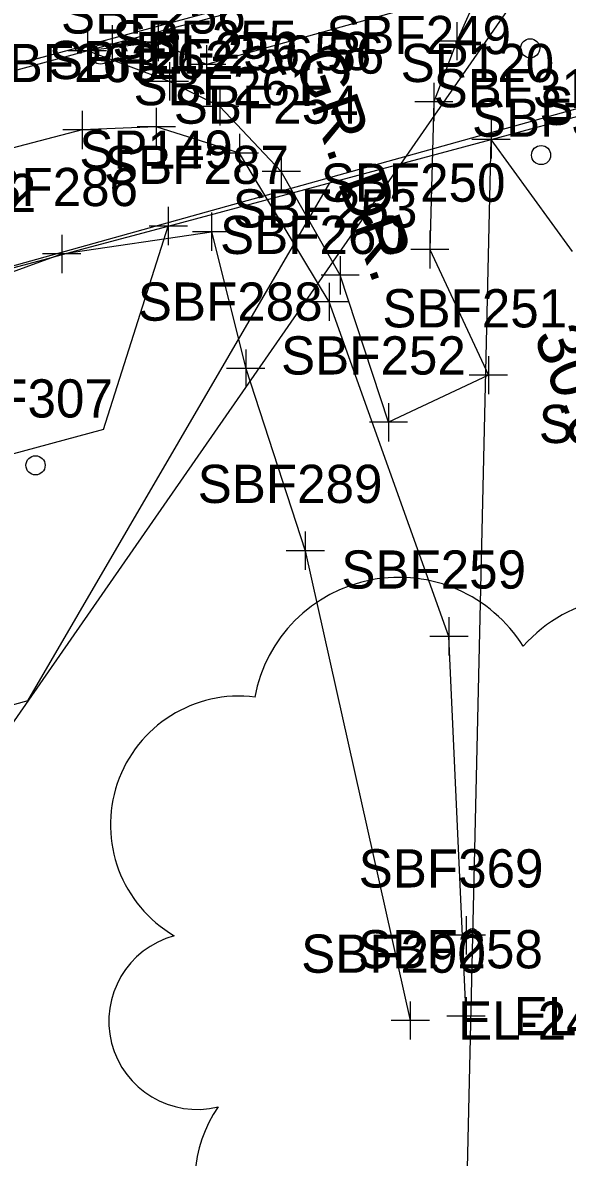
# Model space of a CAD drawing. Extents: x 818717 to 846077, y 440014 to 541392.
# Drawn here: x 831689.4 to 831746.3, y 492977.1 to 493095.8 of the extents above; entities that cross this region are included whole.
import ezdxf

# ---------------------------------------------------------------- set-up
doc = ezdxf.new("R2010")
doc.units = 0
for name, color, linetype in [('SURVEY - CENTERLINE - Preliminary', 7, 'Continuous'), ('SURVEY - CENTERLINE - Preliminary Text', 7, 'Continuous'), ('SURVEY - DRAINAGE - Bridge Hydraulic Data - Points - Numbers', 7, 'Continuous'), ('SURVEY - DTM - Breaklines', 7, 'Continuous'), ('SURVEY - DTM - Breaklines - Points - Elevations', 7, 'Continuous'), ('SURVEY - DTM - Breaklines - Points - Locators', 7, 'Continuous'), ('SURVEY - DTM - Breaklines - Points - Numbers', 7, 'Continuous'), ('SURVEY - DTM - Spot Points - Elevations', 7, 'Continuous'), ('SURVEY - DTM - Spot Points - Locators', 7, 'Continuous'), ('SURVEY - DTM - Spot Points - Point Numbers', 7, 'Continuous'), ('SURVEY - PROPERTY - Property Lines', 7, 'Continuous'), ('SURVEY - PROPERTY - ROW Lines', 7, 'Continuous'), ('SURVEY - PROPERTY - ROW Lines - Points - Locators', 7, 'Continuous'), ('SURVEY - PROPERTY - ROW Lines - Points - Numbers', 7, 'Continuous'), ('SURVEY - PROPERTY - ROW Lines Text', 7, 'Continuous'), ('SURVEY - PROPERTY - Station and Offset Flags', 7, 'Continuous'), ('SURVEY - TRAFFIC CONTROL - Pavement Marking with Text', 7, 'Continuous'), ('SURVEY - TRANSPORTATION - Features', 7, 'Continuous'), ('SURVEY - TRANSPORTATION - Features - Points - Elevations', 7, 'Continuous'), ('SURVEY - TRANSPORTATION - Features - Points - Locators', 7, 'Continuous'), ('SURVEY - TRANSPORTATION - Features - Points - Numbers', 7, 'Continuous'), ('SURVEY - TRANSPORTATION - Features Text', 7, 'Continuous'), ('SURVEY - TRANSPORTATION - Roads', 7, 'Continuous'), ('SURVEY - TRANSPORTATION - Roads - Points - Locators', 7, 'Continuous'), ('SURVEY - UTILITIES - Electric (Overhead) with Text', 7, 'Continuous'), ('SURVEY - VEGETATION - Features - Points - Locators', 7, 'Continuous'), ('SURVEY - VEGETATION - Features - Points - Numbers', 7, 'Continuous'), ('SURVEY - VEGETATION - Features with Text', 7, 'Continuous')]:
    doc.layers.add(name, color=color, linetype=linetype)

msp = doc.modelspace()

# ---------------------------------------------------------------- linework, layer by layer
at = {"layer": 'SURVEY - CENTERLINE - Preliminary'}
msp.add_arc((818719.06, 541389.92), 50000, 284.715407, 285.043654, dxfattribs=at)
msp.add_arc((818719.06, 541389.92), 50000, 284.715407, 285.043654, dxfattribs=at)
msp.add_arc((818719.06, 541389.92), 50000, 284.715407, 285.043654, dxfattribs=at)
msp.add_arc((818719.06, 541389.92), 50000, 284.715407, 285.043654, dxfattribs=at)
at = {"layer": 'SURVEY - CENTERLINE - Preliminary Text'}
msp.add_line((831755.38, 493119.24), (831661.86, 492984.41), dxfattribs=at)
at = {"layer": 'SURVEY - DTM - Breaklines'}
for points in [[(831735.74, 492991.87), (831733.95, 493031.6), (831721.42, 493066.61), (831712.04, 493082.17), (831703.34, 493084.91), (831695.58, 493084.59), (831648.81, 493072.35), (831601.83, 493056.63), (831555.35, 493044.81), (831504.59, 493031.55), (831455.34, 493020.07), (831405.51, 493005.85), (831372.59, 492995.58), (831358.62, 492993.34)], [(831362.8, 492979.81), (831376.24, 492982.73), (831405.77, 492991.28), (831454.7, 493004.49), (831506.17, 493017.71), (831556.95, 493031), (831608.27, 493041.82), (831657.28, 493058.44), (831693.45, 493071.62), (831709.12, 493073.94), (831712.7, 493059.63), (831718.93, 493040.56), (831729.91, 492991.41)]]:
    msp.add_lwpolyline(points, dxfattribs=at)
at = {"layer": 'SURVEY - DTM - Breaklines - Points - Locators'}
for p, q in [((831695.58, 493086.59), (831695.58, 493082.59)), ((831703.34, 493086.91), (831703.34, 493082.91)), ((831705.34, 493084.91), (831701.34, 493084.91)), ((831697.58, 493084.59), (831693.58, 493084.59)), ((831712.04, 493084.17), (831712.04, 493080.17)), ((831714.04, 493082.17), (831710.04, 493082.17)), ((831709.12, 493075.94), (831709.12, 493071.94)), ((831693.45, 493073.62), (831693.45, 493069.62)), ((831711.12, 493073.94), (831707.12, 493073.94)), ((831695.45, 493071.62), (831691.45, 493071.62)), ((831721.42, 493068.61), (831721.42, 493064.61)), ((831723.42, 493066.61), (831719.42, 493066.61)), ((831712.7, 493061.63), (831712.7, 493057.63)), ((831714.7, 493059.63), (831710.7, 493059.63)), ((831718.93, 493042.56), (831718.93, 493038.56)), ((831720.93, 493040.56), (831716.93, 493040.56)), ((831733.95, 493033.6), (831733.95, 493029.6)), ((831735.95, 493031.6), (831731.95, 493031.6)), ((831729.91, 492993.41), (831729.91, 492989.41)), ((831735.74, 492993.87), (831735.74, 492989.87)), ((831731.91, 492991.41), (831727.91, 492991.41)), ((831737.74, 492991.87), (831733.74, 492991.87))]:
    msp.add_line(p, q, dxfattribs=at)
at = {"layer": 'SURVEY - DTM - Spot Points - Locators'}
for centre in [(831697.5, 493092.48), (831742.45, 493093.13), (831743.59, 493081.96), (831690.71, 493049.5)]:
    msp.add_circle(centre, 1, dxfattribs=at)
at = {"layer": 'SURVEY - PROPERTY - Property Lines'}
msp.add_line((831713.28, 491985.29), (831738.36, 493083.6), dxfattribs=at)
at = {"layer": 'SURVEY - PROPERTY - ROW Lines'}
for p, q in [((831738.36, 493083.6), (831806.89, 493102.02)), ((831704.59, 493074.53), (831738.36, 493083.6))]:
    msp.add_line(p, q, dxfattribs=at)
msp.add_arc((818719.06, 541389.92), 50030, 284.715401, 285.043654, dxfattribs=at)
at = {"layer": 'SURVEY - PROPERTY - ROW Lines - Points - Locators'}
for p, q in [((831738.36, 493085.6), (831738.36, 493081.6)), ((831740.36, 493083.6), (831736.36, 493083.6)), ((831704.59, 493076.53), (831704.59, 493072.53)), ((831704.59, 493076.53), (831704.59, 493072.53)), ((831706.59, 493074.53), (831702.59, 493074.53)), ((831706.59, 493074.53), (831702.59, 493074.53))]:
    msp.add_line(p, q, dxfattribs=at)
at = {"layer": 'SURVEY - PROPERTY - ROW Lines Text'}
msp.add_line((831689.91, 493024.86), (831620.13, 493006.1), dxfattribs=at)
msp.add_lwpolyline([(831689.91, 493024.86), (831721.48, 493079.06)], dxfattribs=at)
at = {"layer": 'SURVEY - PROPERTY - Station and Offset Flags'}
msp.add_line((831697.81, 493053.24), (831656.54, 493042.15), dxfattribs=at)
for points in [[(831746.89, 493071.87), (831738.36, 493083.6)], [(831697.81, 493053.24), (831704.59, 493074.53)]]:
    msp.add_lwpolyline(points, dxfattribs=at)
at = {"layer": 'SURVEY - TRAFFIC CONTROL - Pavement Marking with Text'}
msp.add_lwpolyline([(831174.64, 492955.97), (831217.88, 492967.4), (831260.2, 492978.43), (831305.6, 492990.16), (831350.87, 493002.2), (831397.34, 493014.25), (831441.59, 493025.83), (831487.77, 493037.91), (831534.41, 493050.33), (831587.19, 493064.38), (831630.52, 493075.92), (831676.82, 493088.3), (831723.86, 493100.96), (831758.43, 493110.25), (831806.28, 493123.18), (831848.98, 493134.67), (831896.65, 493147.52), (831940.52, 493159.26), (831989.17, 493172.11), (832037.06, 493184.69), (832086.82, 493197.77), (832134.83, 493210.3)], dxfattribs=at)
at = {"layer": 'SURVEY - TRANSPORTATION - Features'}
for points in [[(831745.28, 493105.9), (831745.25, 493104.91), (831735.03, 493101.81), (831732.05, 493097.96), (831708.6, 493091.45), (831703.55, 493093.77), (831696.13, 493092.85)], [(831737.17, 493102.46), (831737.11, 493099.15), (831734.77, 493093.88), (831732.37, 493087.52), (831731.95, 493072.08), (831738.08, 493058.93), (831727.63, 493054), (831722.57, 493069.38), (831716.41, 493080.24), (831709.98, 493087.04), (831704.72, 493089.67), (831696.13, 493092.85)]]:
    msp.add_lwpolyline(points, dxfattribs=at)
at = {"layer": 'SURVEY - TRANSPORTATION - Features - Points - Locators'}
for p, q in [((831703.55, 493095.77), (831703.55, 493091.77)), ((831734.77, 493095.88), (831734.77, 493091.88)), ((831696.13, 493094.85), (831696.13, 493090.85)), ((831705.55, 493093.77), (831701.55, 493093.77)), ((831708.6, 493093.45), (831708.6, 493089.45)), ((831736.77, 493093.88), (831732.77, 493093.88)), ((831698.13, 493092.85), (831694.13, 493092.85)), ((831704.72, 493091.67), (831704.72, 493087.67)), ((831710.6, 493091.45), (831706.6, 493091.45)), ((831706.72, 493089.67), (831702.72, 493089.67)), ((831732.37, 493089.52), (831732.37, 493085.52)), ((831709.98, 493089.04), (831709.98, 493085.04)), ((831734.37, 493087.52), (831730.37, 493087.52)), ((831711.98, 493087.04), (831707.98, 493087.04)), ((831716.41, 493082.24), (831716.41, 493078.24)), ((831718.41, 493080.24), (831714.41, 493080.24)), ((831731.95, 493074.08), (831731.95, 493070.08)), ((831733.95, 493072.08), (831729.95, 493072.08)), ((831722.57, 493071.38), (831722.57, 493067.38)), ((831724.57, 493069.38), (831720.57, 493069.38)), ((831738.08, 493060.93), (831738.08, 493056.93)), ((831740.08, 493058.93), (831736.08, 493058.93)), ((831727.63, 493056), (831727.63, 493052)), ((831729.63, 493054), (831725.63, 493054))]:
    msp.add_line(p, q, dxfattribs=at)
at = {"layer": 'SURVEY - TRANSPORTATION - Roads'}
msp.add_lwpolyline([(831745.28, 493105.9), (831698.71, 493093.56), (831652.79, 493081.06), (831606.96, 493068.69), (831560.39, 493056.4), (831514.16, 493044.16), (831468.16, 493032.15), (831422.28, 493020.03), (831370.82, 493006.55), (831324.94, 492994.38), (831276.67, 492981.92), (831229.94, 492969.71), (831184.11, 492957.61), (831175.07, 492955.18)], dxfattribs=at)
at = {"layer": 'SURVEY - TRANSPORTATION - Roads - Points - Locators'}
for p, q in [((831698.71, 493095.56), (831698.71, 493091.56)), ((831700.71, 493093.56), (831696.71, 493093.56))]:
    msp.add_line(p, q, dxfattribs=at)
at = {"layer": 'SURVEY - UTILITIES - Electric (Overhead) with Text'}
msp.add_lwpolyline([(832667.18, 493331.74), (832415.28, 493266.23), (832147.85, 493195.27), (831907.96, 493131.64), (831666.03, 493064.14), (831375.19, 492986.65), (831101.3, 492913.04)], dxfattribs=at)
at = {"layer": 'SURVEY - VEGETATION - Features - Points - Locators'}
for p, q in [((831735.76, 493002.33), (831735.76, 492998.33)), ((831737.76, 493000.33), (831733.76, 493000.33))]:
    msp.add_line(p, q, dxfattribs=at)
at = {"layer": 'SURVEY - VEGETATION - Features with Text'}
msp.add_circle((831736.39, 493000.58), 0.47, dxfattribs=at)
for centre, radius, start, end in [((831728.71, 493022.45), 15.33, 31.9683, 169.4925), ((831753.17, 493020.52), 15.23, 342.8641, 138.7026), ((831712.01, 493011.9), 13.46, 82.9155, 239.7044), ((831707.62, 492991.35), 9.24, 105.0317, 283.7773), ((831720.83, 492974.69), 13.43, 145.0523, 338.472)]:
    msp.add_arc(centre, radius, start, end, dxfattribs=at)

# ---------------------------------------------------------------- texts
at = {"layer": 'SURVEY - DRAINAGE - Bridge Hydraulic Data - Points - Numbers'}
msp.add_text('SBF333', height=4, dxfattribs=at).set_placement((831743.42, 493085.11))
at = {"layer": 'SURVEY - DTM - Breaklines - Points - Elevations'}
for s, p in [('EL-255.72', (831666.1, 493076)), ('EL-247.74', (831734.91, 492989.41)), ('EL-248.35', (831740.74, 492989.87))]:
    msp.add_text(s, height=4, dxfattribs=at).set_placement(p)
at = {"layer": 'SURVEY - DTM - Breaklines - Points - Numbers'}
for s, p in [('SBF263', (831684.34, 493089.59)), ('SBF262', (831692.1, 493089.91)), ('SBF261', (831700.96, 493087.17)), ('SBF287', (831697.88, 493078.94)), ('SBF286', (831682.1, 493076.62)), ('SBF260', (831710.01, 493071.61)), ('SBF288', (831701.41, 493064.63)), ('SBF289', (831707.67, 493045.56)), ('SBF259', (831722.69, 493036.6)), ('SBF290', (831718.49, 492996.41)), ('SBF258', (831724.45, 492996.87))]:
    msp.add_text(s, height=4, dxfattribs=at).set_placement(p)
at = {"layer": 'SURVEY - DTM - Spot Points - Elevations'}
msp.add_text('EL-256.56', height=4, dxfattribs=at).set_placement((831702.5, 493090.48))
at = {"layer": 'SURVEY - DTM - Spot Points - Point Numbers'}
for s, p in [('SBF317', (831732.35, 493086.96)), ('SBF334', (831736.36, 493083.87)), ('SBF307', (831679.47, 493054.5)), ('SBF318', (831743.35, 493051.83))]:
    msp.add_text(s, height=4, dxfattribs=at).set_placement(p)
at = {"layer": 'SURVEY - PROPERTY - ROW Lines - Points - Numbers'}
for s, p in [('SP120', (831728.9, 493089.6)), ('SP149', (831695.29, 493080.53))]:
    msp.add_text(s, height=4, dxfattribs=at).set_placement(p)
at = {"layer": 'SURVEY - PROPERTY - Station and Offset Flags'}
msp.add_text("30.00'", height=5, rotation=290.101, dxfattribs=at).set_placement((831742.78, 493063.1))
at = {"layer": 'SURVEY - TRANSPORTATION - Features - Points - Elevations'}
msp.add_text('EL-256.58', height=4, dxfattribs=at).set_placement((831701.13, 493090.85))
at = {"layer": 'SURVEY - TRANSPORTATION - Features - Points - Numbers'}
for s, p in [('SBF256', (831693.37, 493094.67)), ('SBF249', (831721.12, 493092.52)), ('SBF255', (831698.74, 493092.04)), ('SBF254', (831705.17, 493085.24)), ('SBF250', (831720.54, 493077.08)), ('SBF253', (831711.33, 493074.38)), ('SBF251', (831726.99, 493063.93)), ('SBF252', (831716.39, 493059))]:
    msp.add_text(s, height=4, dxfattribs=at).set_placement(p)
at = {"layer": 'SURVEY - TRANSPORTATION - Features Text'}
msp.add_text('GR. DR.', height=5, rotation=289.3643, dxfattribs=at).set_placement((831717.72, 493092.15))
at = {"layer": 'SURVEY - VEGETATION - Features - Points - Numbers'}
msp.add_text('SBF369', height=4, dxfattribs=at).set_placement((831724.51, 493005.33))

doc.saveas('drawing.dxf')
